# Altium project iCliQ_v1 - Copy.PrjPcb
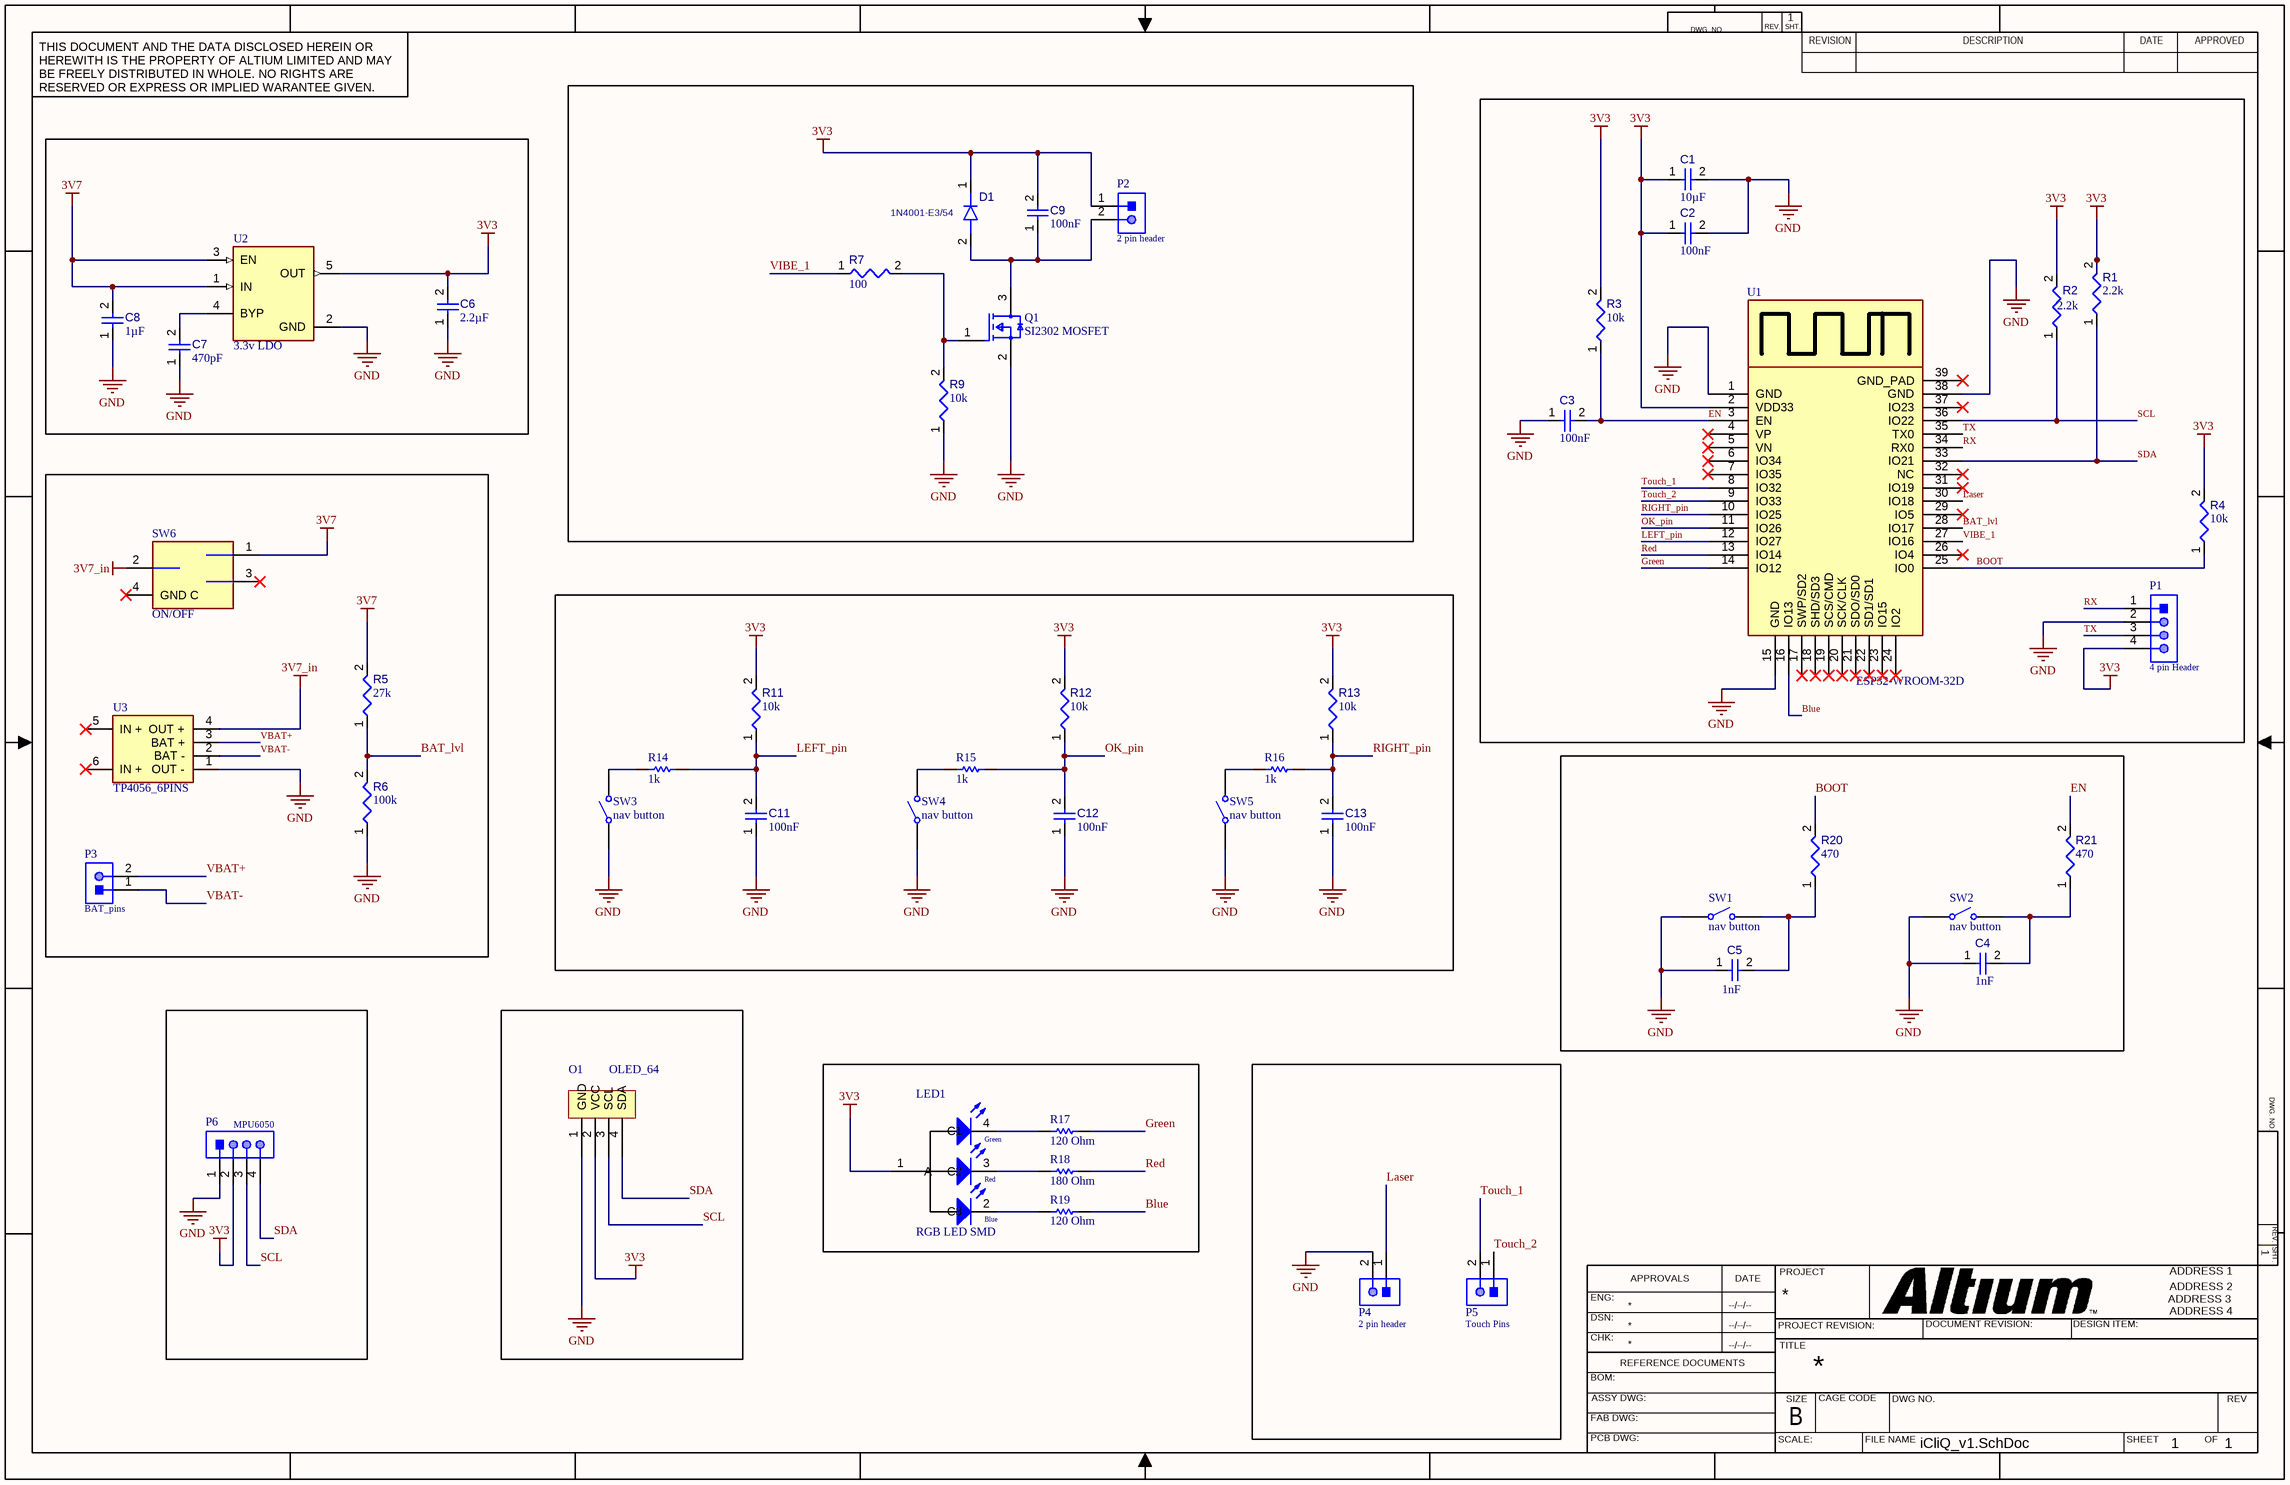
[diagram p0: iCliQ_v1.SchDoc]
1 sheet, 50 parts. Net scope: global (net labels, ports and power ports of the same name join across sheets).
Board files: iCliQ_v1.~(10).PcbDoc, iCliQ_v1.PcbDoc

## Sheet iCliQ_v1.SchDoc
size 431 x 279 mm; Organization: ORGANIZATION; Address1: ADDRESS 1; Address2: ADDRESS 2; Address3: ADDRESS 3; Address4: ADDRESS 4; Revision: -; SheetNumber: 1; SheetTotal: 1; ENG_APP_DATE: --/--/--; DSN_APP_DATE: --/--/--; CHK_APP_DATE: --/--/--

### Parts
C1  value 10µF  [FP-C0805C-DG-IPC_A]  (hidden comment: 10uF 10V 0805)
C2  value 100nF  [CAPC2013X95X50LL10T25]  (hidden comment: Capacitor 100 nF +/-10% 50 V 0805)
C3  value 100nF  [CAPC2013X95X50LL10T25]  (hidden comment: Capacitor 100 nF +/-10% 50 V 0805)
C4  value 1nF  [FP-C0805C-DN-IPC_A]  (hidden comment: 1 nF 50V 0805)
C5  value 1nF  [FP-C0805C-DN-IPC_A]  (hidden comment: 1 nF 50V 0805)
C6  value 2.2µF  [FP-C0805C225K4RACAUTO-IPC_A]  (hidden comment: 2.2 uF 0805)
C7  value 470pF  [FP-C0805C-DN-IPC_A]  (hidden comment: 470 pF 0805)
C8  value 1µF  [CAPC2013X140X50LL20T25]  (hidden comment: 1uF 10V 0805)
C9  value 100nF  [CAPC2013X95X50LL10T25]  (hidden comment: Capacitor 100 nF +/-10% 50 V 0805)
C11  value 100nF  [CAPC2013X95X50LL10T25]  (hidden comment: Capacitor 100 nF +/-10% 50 V 0805)
C12  value 100nF  [CAPC2013X95X50LL10T25]  (hidden comment: Capacitor 100 nF +/-10% 50 V 0805)
C13  value 100nF  [CAPC2013X95X50LL10T25]  (hidden comment: Capacitor 100 nF +/-10% 50 V 0805)
D1  1N4001-E3/54  [FP-1N4001-E3-54-MFG]
LED1  RGB LED SMD  [3528_A]
O1  OLED_64  [OLED_SSD1306_64]
P1  4 pin Header  [61300411121]
P2  2 pin header  [61300211121]
P3  BAT_pins  [61300211121]
P4  2 pin header  [61300211121]
P5  Touch Pins  [61300211121]
P6  MPU6050  [61300411121]
Q1  SI2302 MOSFET  [FP-S-03946-MFG]
R1  value 2.2k  [RESC2013X60X40LL20T25]  (hidden comment: 2.2K 0805)
R2  value 2.2k  [RESC2013X60X40LL20T25]  (hidden comment: 2.2K 0805)
R3  value 10k  [RESC2013X60X35LL10T20]  (hidden comment: 10K 0805)
R4  value 10k  [RESC2013X60X35LL10T20]  (hidden comment: 10K 0805)
R5  value 27k  [RESC2013X60X40LL20T25]  (hidden comment: 27K 0805)
R6  value 100k  [RESC2013X70X40ML20T20]  (hidden comment: Resistor 100k +/-1% 0805 125 mW)
R7  value 100  [RESC2013X60X40LL20T25]  (hidden comment: 100 Ohm 0805)
R9  value 10k  [RESC2013X60X35LL10T20]  (hidden comment: 10K 0805)
R11  value 10k  [RESC2013X60X35LL10T20]  (hidden comment: 10K 0805)
R12  value 10k  [RESC2013X60X35LL10T20]  (hidden comment: 10K 0805)
R13  value 10k  [RESC2013X60X35LL10T20]  (hidden comment: 10K 0805)
R14  value 1k  [RESC2013X70X40NL20T20]  (hidden comment: Resistor 1K +/-5% 0805 500 mW.)
R15  value 1k  [RESC2013X70X40NL20T20]  (hidden comment: Resistor 1K +/-5% 0805 500 mW.)
R16  value 1k  [RESC2013X70X40NL20T20]  (hidden comment: Resistor 1K +/-5% 0805 500 mW.)
R17  value 120 Ohm  [RESC2013X50X35ML15T15]  (hidden comment: Resistor 0R +/- 1% 0805 125 mW)
R18  value 180 Ohm  [RESC2013X50X35ML15T15]  (hidden comment: Resistor 0R +/- 1% 0805 125 mW)
R19  value 120 Ohm  [RESC2013X50X35ML15T15]  (hidden comment: Resistor 0R +/- 1% 0805 125 mW)
R20  value 470  [RESC0805(2012)_L]  (hidden comment: Resistor 470R +/-5% 0805 125 mW)
R21  value 470  [RESC0805(2012)_L]  (hidden comment: Resistor 470R +/-5% 0805 125 mW)
SW1  nav button  [434121050816]
SW2  nav button  [434121050816]
SW3  nav button  [434121050816]
SW4  nav button  [434121050816]
SW5  nav button  [434121050816]
SW6  Part Number: ON/OFF  [ALPS_SSSS811101_0]  (hidden comment: Switch_ALPS_SSSS811101_eec)
U1  ESP32-WROOM-32D  [ESP32-WROOM-32D]
U2  3.3v LDO  [FP-SOT23-5LD-PL-1-MFG]
U3  TP4056_6PINS  [TP4056_6PINs]

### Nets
3V3: C1.1 C2.1 C6.2 C9.2 D1.1(K) LED1.1(A) O1.2(VCC) P1.4 P2.1 P6.2 R1.2 R2.2 R3.2 R4.2 R11.2 R12.2 R13.2 U1.2(VDD33) U2.5(OUT)
3V7: C8.2 R5.2 SW6.1 U2.1(IN) U2.3(EN)
3V7_in: SW6.2(C) U3.4(OUT_+)
GND: C1.2 C2.2 C3.1 C4.1 C5.1 C6.1 C7.1 C8.1 C11.1 C12.1 C13.1 O1.1(GND) P1.2 P4.2 P6.1 Q1.2(S) R6.1 R9.1 SW1.1 SW2.1 SW3.1 SW4.1 SW5.1 U1.1(GND) U1.15(GND) U1.38(GND) U2.2(GND) U3.1(OUT_-)
BAT_lvl: R5.1 R6.2 U1.28(IO17)
Blue: R19.2 U1.16(IO13)
BOOT: R4.1 R20.2 U1.25(IO0)
EN: C3.2 R3.1 R21.2 U1.3(EN)
Green: R17.2 U1.14(IO12)
Laser: P4.1 U1.30(IO18)
LEFT_pin: C11.2 R11.1 R14.2 U1.12(IO27)
OK_pin: C12.2 R12.1 R15.2 U1.11(IO26)
Red: R18.2 U1.13(IO14)
RIGHT_pin: C13.2 R13.1 R16.2 U1.10(IO25)
RX: P1.1 U1.34(RX0)
SCL: O1.3(SCL) P6.3 R2.1 U1.36(IO22)
SDA: O1.4(SDA) P6.4 R1.1 U1.33(IO21)
Touch_1: P5.2 U1.8(IO32)
Touch_2: P5.1 U1.9(IO33)
TX: P1.3 U1.35(TX0)
VBAT+: P3.2 U3.3(BAT_+)
VBAT-: P3.1 U3.2(BAT_-)
VIBE_1: R7.1 U1.27(IO16)
NetC4_2: C4.2 R21.1 SW2.2
NetC5_2: C5.2 R20.1 SW1.2
NetC7_2: C7.2 U2.4(BYP)
NetC9_1: C9.1 D1.2(A) P2.2 Q1.3(D)
NetLED1_2: LED1.2(C3) R19.1
NetLED1_3: LED1.3(C2) R18.1
NetLED1_4: LED1.4(C1) R17.1
NetQ1_1: Q1.1(G) R7.2 R9.2
NetR14_1: R14.1 SW3.2
NetR15_1: R15.1 SW4.2
NetR16_1: R16.1 SW5.2

Not connected (* = marked no-connect by the designer): SW6 3* 4(GND_C)*; U1 4(VP)* 5(VN)* 6(IO34)* 7(IO35)* 17(SWP/SD2)* 18(SHD/SD3)* 19(SCS/CMD)* 20(SCK/CLK)* 21(SDO/SD0)* 22(SD1/SD1)* 23(IO15)* 24(IO2)* 26(IO4)* 29(IO5)* 31(IO19)* 32(NC)* 37(IO23)* 39(GND_PAD)*; U3 5(IN_+)* 6(IN_+)*

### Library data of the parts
C1 = CMP-001-00085-1: Ceramic Capacitor, Multilayer, Ceramic, 10V, 10% +Tol, 10% -Tol, X5R, 15% TC, 10uF, Surface Mount, 0805
C2 C3 C9 C11-C13 = CMP-001-00018-6: Chip Capacitor, 100 nF, +/- 10%, 50 V, 0805 (2012 Metric); Capacitor Type: Ceramic; Voltage Rating: 50V
C4 C5 = CMP-001-00087-1: Ceramic Capacitor, Multilayer, Ceramic, 50V, 5% +Tol, 5% -Tol, C0G, 30ppm/Cel TC, 0.001uF, Surface Mount, 0805
C6 = CMP-001-00091-1: Ceramic Capacitor, Multilayer, Ceramic, 16V, 10% +Tol, 10% -Tol, X7R, 15% TC, 2.2uF, Surface Mount, 0805
C7 = CMP-001-00088-1: Ceramic Capacitor, Multilayer, Ceramic, 50V, 10% +Tol, 10% -Tol, X7R, 15% TC, 0.00047uF, Surface Mount, 0805
C8 = CMP-001-00086-1: Ceramic Capacitor, Multilayer, Ceramic, 10V, 5% +Tol, 5% -Tol, X8L, 15% TC, 1uF, Surface Mount, 0805
D1 = CMP-004-00031-1: Rectifier Diode, 1 Phase, 1 Element, 1A, 50V V(RRM), Silicon, DO-204AL; Forward Voltage: 1.1V
LED1 = CMP-00030-00002-1: Triple Color LED, Red/green/blue, Water Clear
O1 = OLED_64: JST (JAPAN SOLDERLESS TERMINALS) - B8B-XH-A (LF)(SN) - HEADER, VERTICAL, 8WAY; No of Positions: 8; Pitch: 2.5 mm; Style/Orientation: Straight Header/Plug
P1 P6 = CMP-002-00078-1: Board Connector, 4 Contact(s), 1 Row(s), Male, Straight, 0.1 inch Pitch, Solder Terminal, Locking, Black Insulator, Plug
P2-P5 = CMP-002-00075-1: Board Connector, 2 Contact(s), 1 Row(s), Male, Straight, 0.1 inch Pitch, Solder Terminal, Locking, Black Insulator, Plug
Q1 = CMP-011-00017-1: Small Signal Field-Effect Transistor, 2.6A I(D), 20V, 1-Element, N-Channel, Silicon, Metal-oxide Semiconductor FET, TO-236AB
R1 R2 = CMP-009-00187-1: Fixed Resistor, Thin Film, 0.125W, 2200ohm, 100V, 0.5% +/-Tol, 25ppm/Cel, Surface Mount, 0805; Power: 125mW
R3 R4 R11-R13 = CMP-009-00180-1: Fixed Resistor, Metal Glaze/thick Film, 0.125W, 10000ohm, 150V, 1% +/-Tol, 100ppm/Cel, Surface Mount, 0805; Power: 125mW
R5 = CMP-009-00191-1: Fixed Resistor, Thin Film, 0.125W, 27000ohm, 100V, 0.1% +/-Tol, 25ppm/Cel, Surface Mount, 0805; Power: 125mW
R6 = CMP-009-00024-5: Chip Resistor, 100 KOhm, +/- 1%, 0.125 W, -55 to 155 degC, 0805 (2012 Metric); Power: 125mW; Voltage Rating: 150V
R7 = CMP-009-00189-1: Fixed Resistor, Thin Film, 0.125W, 100ohm, 100V, 0.1% +/-Tol, 25ppm/Cel, Surface Mount, 0805; Power: 125mW
R9 = CMP-009-00181-1: Fixed Resistor, Metal Glaze/thick Film, 0.125W, 10000ohm, 150V, 1% +/-Tol, 100ppm/Cel, Surface Mount, 0805; Power: 125mW
R14-R16 = CMP-009-00178-1: Fixed Resistor, Metal Glaze/thick Film, 0.5W, 1000ohm, 400V, 5% +/-Tol, 200ppm/Cel, Surface Mount, 0805; Power: 500mW
R17-R19 = CMP-009-00001-5: Chip Resistor, 0 Ohm, +/- 1%, 125 mW, -55 to 155 degC, 0805 (2012 Metric); Voltage Rating: 150V; Power: 125mW
R20 R21 = CMP-009-00122-3: Chip Resistor, 470 Ohms, +/-5%, 125 mW, -55 to 155 degC, 0805; Tolerance: 5%; Power: 125mW
SW1-SW5 = CMP-011-00016-1: Keypad Switch, 1 Switches, SPST, Momentary-tactile, 0.05A, 12VDC, 2.06N, Solder Terminal, Surface Mount-straight
SW6 = Switch_ALPS_SSSS811101_eec: Manufacturer: ALPS; Contact resistance: 70mΩ; Rating (max.)/(min.) (Resistive load): 0.3A 5V DC/50µA 3V DC
U1 = CMP-016-000004-1: Chip SMD 39 Pads Wifi 2.4GHz BLE 4.2 18x25.5mm w/ Antenna.
U2 = CMP-021-000001-1: IC REG LDO 3.3V 0.5A SOT23-5
U3 = CMP-00029-00003-2: MODULE BATTERY CHARGER 6 PINS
